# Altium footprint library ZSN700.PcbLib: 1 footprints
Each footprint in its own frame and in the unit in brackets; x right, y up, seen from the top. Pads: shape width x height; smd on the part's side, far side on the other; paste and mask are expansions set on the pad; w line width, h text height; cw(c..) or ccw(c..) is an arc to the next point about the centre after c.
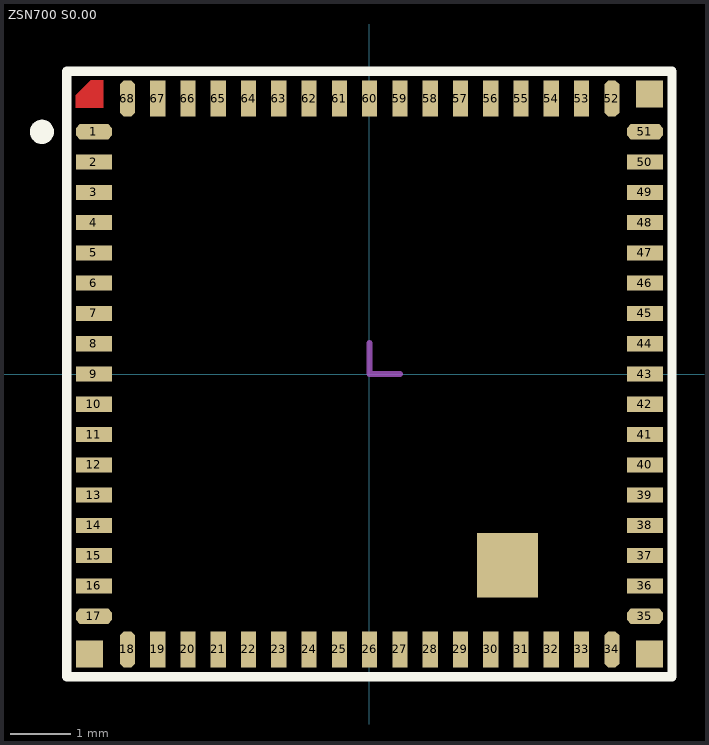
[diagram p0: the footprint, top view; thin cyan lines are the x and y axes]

## ZSN700 S0.00 [mm] "ZLGLIB_"
height 0.95
pads (72):
  oct 0.6x0.25 smd mask+0.051: 1(-4.55,4) 17(-4.55,-4) 35(4.55,-4) 51(4.55,4)
  rect 0.6x0.25 smd mask+0.051: 2(-4.55,3.5) 3(-4.55,3) 4(-4.55,2.5) 5(-4.55,2) 6(-4.55,1.5) 7(-4.55,1) 8(-4.55,0.5) 9(-4.55,0) 10(-4.55,-0.5) 11(-4.55,-1) 12(-4.55,-1.5) 13(-4.55,-2) 14(-4.55,-2.5) 15(-4.55,-3) 16(-4.55,-3.5) 36(4.55,-3.5) 37(4.55,-3) 38(4.55,-2.5) 39(4.55,-2) 40(4.55,-1.5) 41(4.55,-1) 42(4.55,-0.5) 43(4.55,0) 44(4.55,0.5) 45(4.55,1) 46(4.55,1.5) 47(4.55,2) 48(4.55,2.5) 49(4.55,3) 50(4.55,3.5)
  oct 0.25x0.6 smd mask+0.051: 18(-3.997,-4.55) 34(4.003,-4.55) 52(4.003,4.55) 68(-3.997,4.55)
  rect 0.25x0.6 smd mask+0.051: 19(-3.497,-4.55) 20(-2.997,-4.55) 21(-2.497,-4.55) 22(-1.997,-4.55) 23(-1.497,-4.55) 24(-0.997,-4.55) 25(-0.497,-4.55) 26(0.003,-4.55) 27(0.503,-4.55) 28(1.003,-4.55) 29(1.503,-4.55) 30(2.003,-4.55) 31(2.503,-4.55) 32(3.003,-4.55) 33(3.503,-4.55) 53(3.503,4.55) 54(3.003,4.55) 55(2.503,4.55) 56(2.003,4.55) 57(1.503,4.55) 58(1.003,4.55) 59(0.503,4.55) 60(0.003,4.55) 61(-0.497,4.55) 62(-0.997,4.55) 63(-1.497,4.55) 64(-1.997,4.55) 65(-2.497,4.55) 66(-2.997,4.55) 67(-3.497,4.55)
  rect 0.45x0.45 smd mask+0.051: ""(-4.625,-4.625) ""(4.625,-4.625) ""(4.625,4.625)
  rect 1x1.07 smd: ""(2.28,-3.16)
Top Layer:
  region: -4.85,4.4 -4.85,4.6 -4.6,4.85 -4.4,4.85 -4.4,4.4
Top Overlay:
  circle w0.2: c-5.41,4 r0.1
  lines w0.15: -5,-5 -5,5 5,5 5,-5 -5,-5
Mechanical 15:
  lines w0.1: 0,0.508 0,0 0.508,0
